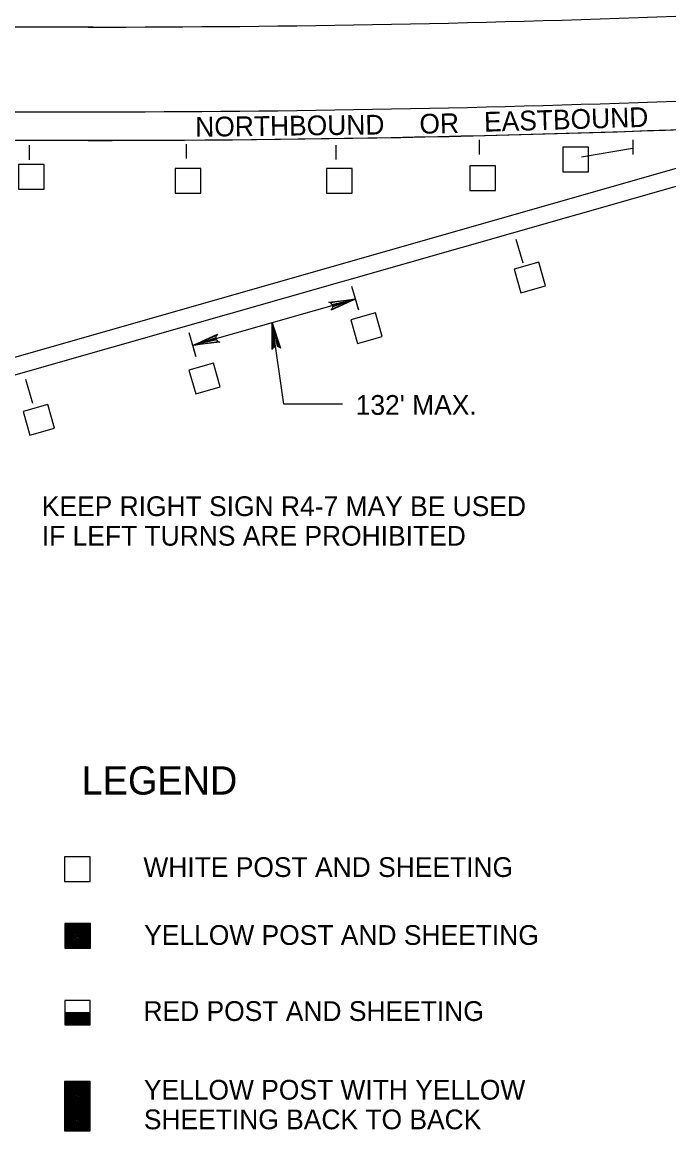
# Model space of a CAD drawing. Extents: x 640253 to 641999, y 298458 to 299646.
# Drawn here: x 641608.8 to 641707.1, y 299250.5 to 299419 of the extents above; entities that cross this region are included whole.
import ezdxf

# ---------------------------------------------------------------- set-up
doc = ezdxf.new("R2010")
doc.units = 0
doc.layers.add('2', color=7, linetype='Continuous')

msp = doc.modelspace()

# ---------------------------------------------------------------- linework, layer by layer
at = {"layer": '2'}
for p, q in [((641249.69, 299418.29), (641619.6, 299418.29)), ((641548.91, 299405.41), (641619.17, 299405.41)), ((641589.09, 299362.8), (641732.18, 299403.67)), ((641442.79, 299401.07), (641619.17, 299401.07)), ((641678.3, 299398.93), (641678.3, 299401.14)), ((641701.67, 299398.93), (641701.67, 299401.14)), ((641609.94, 299398.12), (641609.94, 299400.32)), ((641633.82, 299398.29), (641633.82, 299400.5)), ((641656.54, 299398.14), (641656.54, 299400.34)), ((641693.8, 299398.55), (641701.56, 299399.86)), ((641593.29, 299361.29), (641724.82, 299398.87)), ((641683.86, 299386.04), (641684.92, 299382.43)), ((641658.86, 299378.91), (641659.92, 299375.28)), ((641659.32, 299377.36), (641659.87, 299375.4)), ((641659.44, 299376.93), (641634.84, 299369.91)), ((641634.15, 299371.84), (641635.21, 299368.21)), ((641634.6, 299370.3), (641635.15, 299368.33)), ((641609.34, 299364.76), (641610.39, 299361.13))]:
    msp.add_line(p, q, dxfattribs=at)
for points in [[(641690.96, 299396.28), (641694.86, 299396.28), (641694.86, 299400.03), (641690.96, 299400.03)], [(641608.28, 299393.66), (641612.18, 299393.66), (641612.18, 299397.41), (641608.28, 299397.41)], [(641632.08, 299393.05), (641635.98, 299393.05), (641635.98, 299396.8), (641632.08, 299396.8)], [(641655.06, 299393.05), (641658.96, 299393.05), (641658.96, 299396.8), (641655.06, 299396.8)], [(641676.85, 299393.46), (641680.74, 299393.46), (641680.74, 299397.2), (641676.85, 299397.2)], [(641684.6, 299377.87), (641688.35, 299378.94), (641687.32, 299382.54), (641683.57, 299381.47)], [(641659.8, 299370.2), (641663.55, 299371.27), (641662.52, 299374.87), (641658.77, 299373.8)], [(641635.2, 299362.53), (641638.94, 299363.6), (641637.91, 299367.2), (641634.17, 299366.13)], [(641609.99, 299356.27), (641613.74, 299357.34), (641612.71, 299360.94), (641608.96, 299359.87)], [(641615.25, 299288.42), (641619.15, 299288.42), (641619.15, 299292.16), (641615.25, 299292.16)]]:
    msp.add_lwpolyline(points, close=True, dxfattribs=at)
for points in [[(641655.67, 299376.35), (641655.88, 299376.12), (641659.44, 299376.93), (641655.67, 299376.35), (641655.44, 299376.45), (641659.44, 299376.93), (641655.99, 299375.76), (641655.93, 299375.46), (641659.44, 299376.93), (641655.79, 299375.23), (641655.93, 299375.46)], [(641646.94, 299369.51), (641647.19, 299369.7), (641646.8, 299373.32), (641646.94, 299369.51), (641646.81, 299369.29), (641646.8, 299373.32), (641647.56, 299369.76), (641647.85, 299369.67), (641646.8, 299373.32), (641648.06, 299369.5), (641647.85, 299369.67)], [(641657.49, 299360.96), (641648.6, 299360.96), (641646.8, 299373.32)], [(641638.61, 299370.5), (641638.4, 299370.72), (641634.84, 299369.91), (641638.61, 299370.5), (641638.84, 299370.39), (641634.84, 299369.91), (641638.29, 299371.08), (641638.35, 299371.38), (641634.84, 299369.91), (641638.49, 299371.61), (641638.35, 299371.38)], [(641615.29, 299278.28), (641619.19, 299278.28), (641619.19, 299282.03), (641615.29, 299282.03), (641615.29, 299278.28), (641619.13, 299281.96), (641615.35, 299281.96), (641615.35, 299278.33), (641619.13, 299278.33), (641619.13, 299281.89), (641615.43, 299281.89), (641615.43, 299278.4), (641619.05, 299278.4), (641619.04, 299281.8), (641615.5, 299281.8), (641615.5, 299278.46), (641618.98, 299278.46), (641618.98, 299281.74), (641615.57, 299281.74), (641615.57, 299278.52), (641618.9, 299278.52), (641618.89, 299281.67), (641615.64, 299281.67), (641615.63, 299278.57), (641618.83, 299278.59), (641618.81, 299281.6), (641615.7, 299281.6), (641615.69, 299278.64), (641618.77, 299278.66), (641618.75, 299281.53), (641615.77, 299281.53), (641615.75, 299278.72), (641618.68, 299278.74), (641618.68, 299281.44), (641615.86, 299281.45), (641615.82, 299278.77), (641618.58, 299278.82), (641618.59, 299281.38), (641615.94, 299281.38), (641615.9, 299278.84), (641618.5, 299278.88), (641618.5, 299281.32), (641616.02, 299281.31), (641615.98, 299278.88), (641618.41, 299278.95), (641618.41, 299281.25), (641616.1, 299281.22), (641616.06, 299280.12), (641616.06, 299278.95), (641618.34, 299279.02), (641618.31, 299281.15), (641616.18, 299281.11), (641616.14, 299279.02), (641618.25, 299279.09), (641618.22, 299281.07), (641616.29, 299281.01), (641616.25, 299279.11), (641618.12, 299279.16), (641618.1, 299280.94), (641616.43, 299280.91), (641616.37, 299279.24), (641617.98, 299279.27), (641617.95, 299280.84), (641616.58, 299280.78), (641616.51, 299279.35), (641616.51, 299279.35), (641617.83, 299279.4), (641617.82, 299280.69), (641616.72, 299280.65), (641616.65, 299279.48), (641617.67, 299279.54), (641617.68, 299280.54), (641616.85, 299280.52), (641616.82, 299279.64), (641617.52, 299279.67), (641617.49, 299280.41), (641617.02, 299280.38), (641617, 299279.77), (641617.34, 299279.8), (641617.34, 299280.25), (641617.2, 299280.28), (641617.18, 299279.92)], [(641615.29, 299268.49), (641619.18, 299268.49), (641619.18, 299270.36), (641615.29, 299270.36), (641615.29, 299266.62), (641619.18, 299266.62), (641619.18, 299268.41), (641615.36, 299268.41), (641615.36, 299266.67), (641619.12, 299266.67), (641619.12, 299268.34), (641615.43, 299268.34), (641615.43, 299266.74), (641619.04, 299266.74), (641619.04, 299268.27), (641615.5, 299268.27), (641615.5, 299266.82), (641618.96, 299266.82), (641618.96, 299268.19), (641615.58, 299268.19), (641615.58, 299266.9), (641618.87, 299266.9), (641618.87, 299268.11), (641615.66, 299268.11), (641615.65, 299266.98), (641618.78, 299266.98), (641618.77, 299268.02), (641615.74, 299268.02), (641615.75, 299267.05), (641618.7, 299267.05), (641618.7, 299267.94), (641615.83, 299267.94), (641615.83, 299267.15), (641618.59, 299267.15), (641618.59, 299267.84), (641615.93, 299267.84), (641615.93, 299267.24), (641618.48, 299267.24), (641618.47, 299267.75), (641616.02, 299267.75), (641616.02, 299267.34), (641618.37, 299267.34), (641618.37, 299267.63), (641616.13, 299267.63), (641616.13, 299267.44), (641618.25, 299267.44), (641618.25, 299267.53), (641616.22, 299267.54)], [(641615.26, 299254.27), (641619.16, 299254.27), (641619.16, 299258.02), (641615.26, 299258.02), (641615.26, 299254.27), (641619.09, 299257.95), (641615.32, 299257.95), (641615.32, 299254.32), (641619.09, 299254.32), (641619.09, 299257.88), (641615.4, 299257.88), (641615.4, 299254.39), (641619.01, 299254.39), (641619.01, 299257.79), (641615.47, 299257.79), (641615.47, 299254.45), (641618.95, 299254.45), (641618.95, 299257.74), (641615.53, 299257.74), (641615.53, 299254.51), (641618.87, 299254.52), (641618.86, 299257.67), (641615.6, 299257.67), (641615.59, 299254.57), (641618.8, 299254.59), (641618.78, 299257.59), (641615.67, 299257.59), (641615.66, 299254.63), (641618.73, 299254.65), (641618.71, 299257.52), (641615.74, 299257.52), (641615.72, 299254.71), (641618.64, 299254.73), (641618.64, 299257.43), (641615.83, 299257.44), (641615.79, 299254.76), (641618.55, 299254.81), (641618.56, 299257.38), (641615.91, 299257.38), (641615.87, 299254.83), (641618.47, 299254.87), (641618.47, 299257.32), (641615.98, 299257.3), (641615.94, 299254.87), (641618.38, 299254.94), (641618.37, 299257.24), (641616.07, 299257.21), (641616.02, 299256.11), (641616.02, 299254.94), (641618.3, 299255.01), (641618.27, 299257.14), (641616.15, 299257.1), (641616.11, 299255.01), (641618.22, 299255.08), (641618.19, 299257.06), (641616.26, 299257), (641616.22, 299255.1), (641618.09, 299255.15), (641618.07, 299256.94), (641616.39, 299256.9), (641616.33, 299255.23), (641617.94, 299255.26), (641617.92, 299256.83), (641616.55, 299256.77), (641616.47, 299255.35), (641616.48, 299255.35), (641617.8, 299255.4), (641617.79, 299256.68), (641616.68, 299256.64), (641616.62, 299255.48), (641617.64, 299255.53), (641617.65, 299256.53), (641616.82, 299256.51), (641616.78, 299255.63), (641617.48, 299255.66), (641617.46, 299256.4), (641616.99, 299256.37), (641616.97, 299255.77), (641617.31, 299255.8), (641617.31, 299256.24), (641617.16, 299256.27), (641617.14, 299255.91)], [(641615.26, 299250.53), (641619.16, 299250.53), (641619.16, 299254.28), (641615.26, 299254.28), (641615.26, 299250.53), (641619.09, 299254.21), (641615.32, 299254.21), (641615.32, 299250.58), (641619.09, 299250.58), (641619.09, 299254.14), (641615.4, 299254.14), (641615.4, 299250.65), (641619.02, 299250.65), (641619.01, 299254.05), (641615.47, 299254.05), (641615.47, 299250.71), (641618.95, 299250.71), (641618.95, 299253.99), (641615.54, 299253.99), (641615.54, 299250.77), (641618.87, 299250.77), (641618.86, 299253.92), (641615.61, 299253.92), (641615.59, 299250.82), (641618.8, 299250.84), (641618.78, 299253.85), (641615.67, 299253.85), (641615.66, 299250.89), (641618.73, 299250.91), (641618.72, 299253.78), (641615.74, 299253.78), (641615.72, 299250.97), (641618.65, 299250.99), (641618.65, 299253.69), (641615.83, 299253.7), (641615.79, 299251.02), (641618.55, 299251.07), (641618.56, 299253.63), (641615.91, 299253.63), (641615.87, 299251.09), (641618.47, 299251.13), (641618.47, 299253.57), (641615.98, 299253.55), (641615.95, 299251.13), (641618.38, 299251.19), (641618.37, 299253.5), (641616.07, 299253.47), (641616.02, 299252.37), (641616.02, 299251.19), (641618.31, 299251.27), (641618.28, 299253.4), (641616.15, 299253.36), (641616.11, 299251.27), (641618.22, 299251.34), (641618.19, 299253.32), (641616.26, 299253.26), (641616.22, 299251.36), (641618.09, 299251.41), (641618.07, 299253.19), (641616.39, 299253.15), (641616.34, 299251.49), (641617.94, 299251.52), (641617.92, 299253.09), (641616.55, 299253.03), (641616.47, 299251.6), (641616.48, 299251.6), (641617.8, 299251.65), (641617.79, 299252.94), (641616.69, 299252.9), (641616.62, 299251.73), (641617.64, 299251.79), (641617.65, 299252.78), (641616.82, 299252.77), (641616.78, 299251.89), (641617.49, 299251.92), (641617.46, 299252.66), (641616.99, 299252.63), (641616.97, 299252.02), (641617.31, 299252.05), (641617.31, 299252.5), (641617.17, 299252.53), (641617.14, 299252.17)]]:
    msp.add_lwpolyline(points, dxfattribs=at)
for radius, end in [(2448.22, 274.31789), (2461.1, 274.29526), (2465.44, 272.72047), (2465.43, 272.63682)]:
    msp.add_arc((641618.76, 301866.5), radius, 270.0023, end, dxfattribs=at)

# ---------------------------------------------------------------- texts
for s, rotation, p in [('EASTBOUND', 1.7407, (641679.05, 299402.37)), ('NORTHBOUND', 0.7104, (641635.14, 299401.61)), ('OR', 1.2267, (641669.22, 299402.06))]:
    msp.add_text(s, height=3, rotation=rotation, dxfattribs=at).set_placement(p)
for s, height, p in [("132' MAX.", 3, (641659.51, 299359.35)), ('KEEP RIGHT SIGN R4-7 MAY BE USED', 3, (641611.82, 299343.96)), ('IF LEFT TURNS ARE PROHIBITED', 3, (641611.82, 299339.46)), ('LEGEND', 4.3, (641617.87, 299301.63)), ('WHITE POST AND SHEETING', 3, (641627.25, 299289.11)), ('YELLOW POST AND SHEETING', 3, (641627.37, 299278.79)), ('RED POST AND SHEETING', 3, (641627.26, 299267.23)), ('YELLOW POST WITH YELLOW', 3, (641627.32, 299255.27)), ('SHEETING BACK TO BACK', 3, (641627.32, 299250.77))]:
    msp.add_text(s, height=height, dxfattribs=at).set_placement(p)

doc.saveas('drawing.dxf')
